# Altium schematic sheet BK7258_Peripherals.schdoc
size 440 x 214 mm
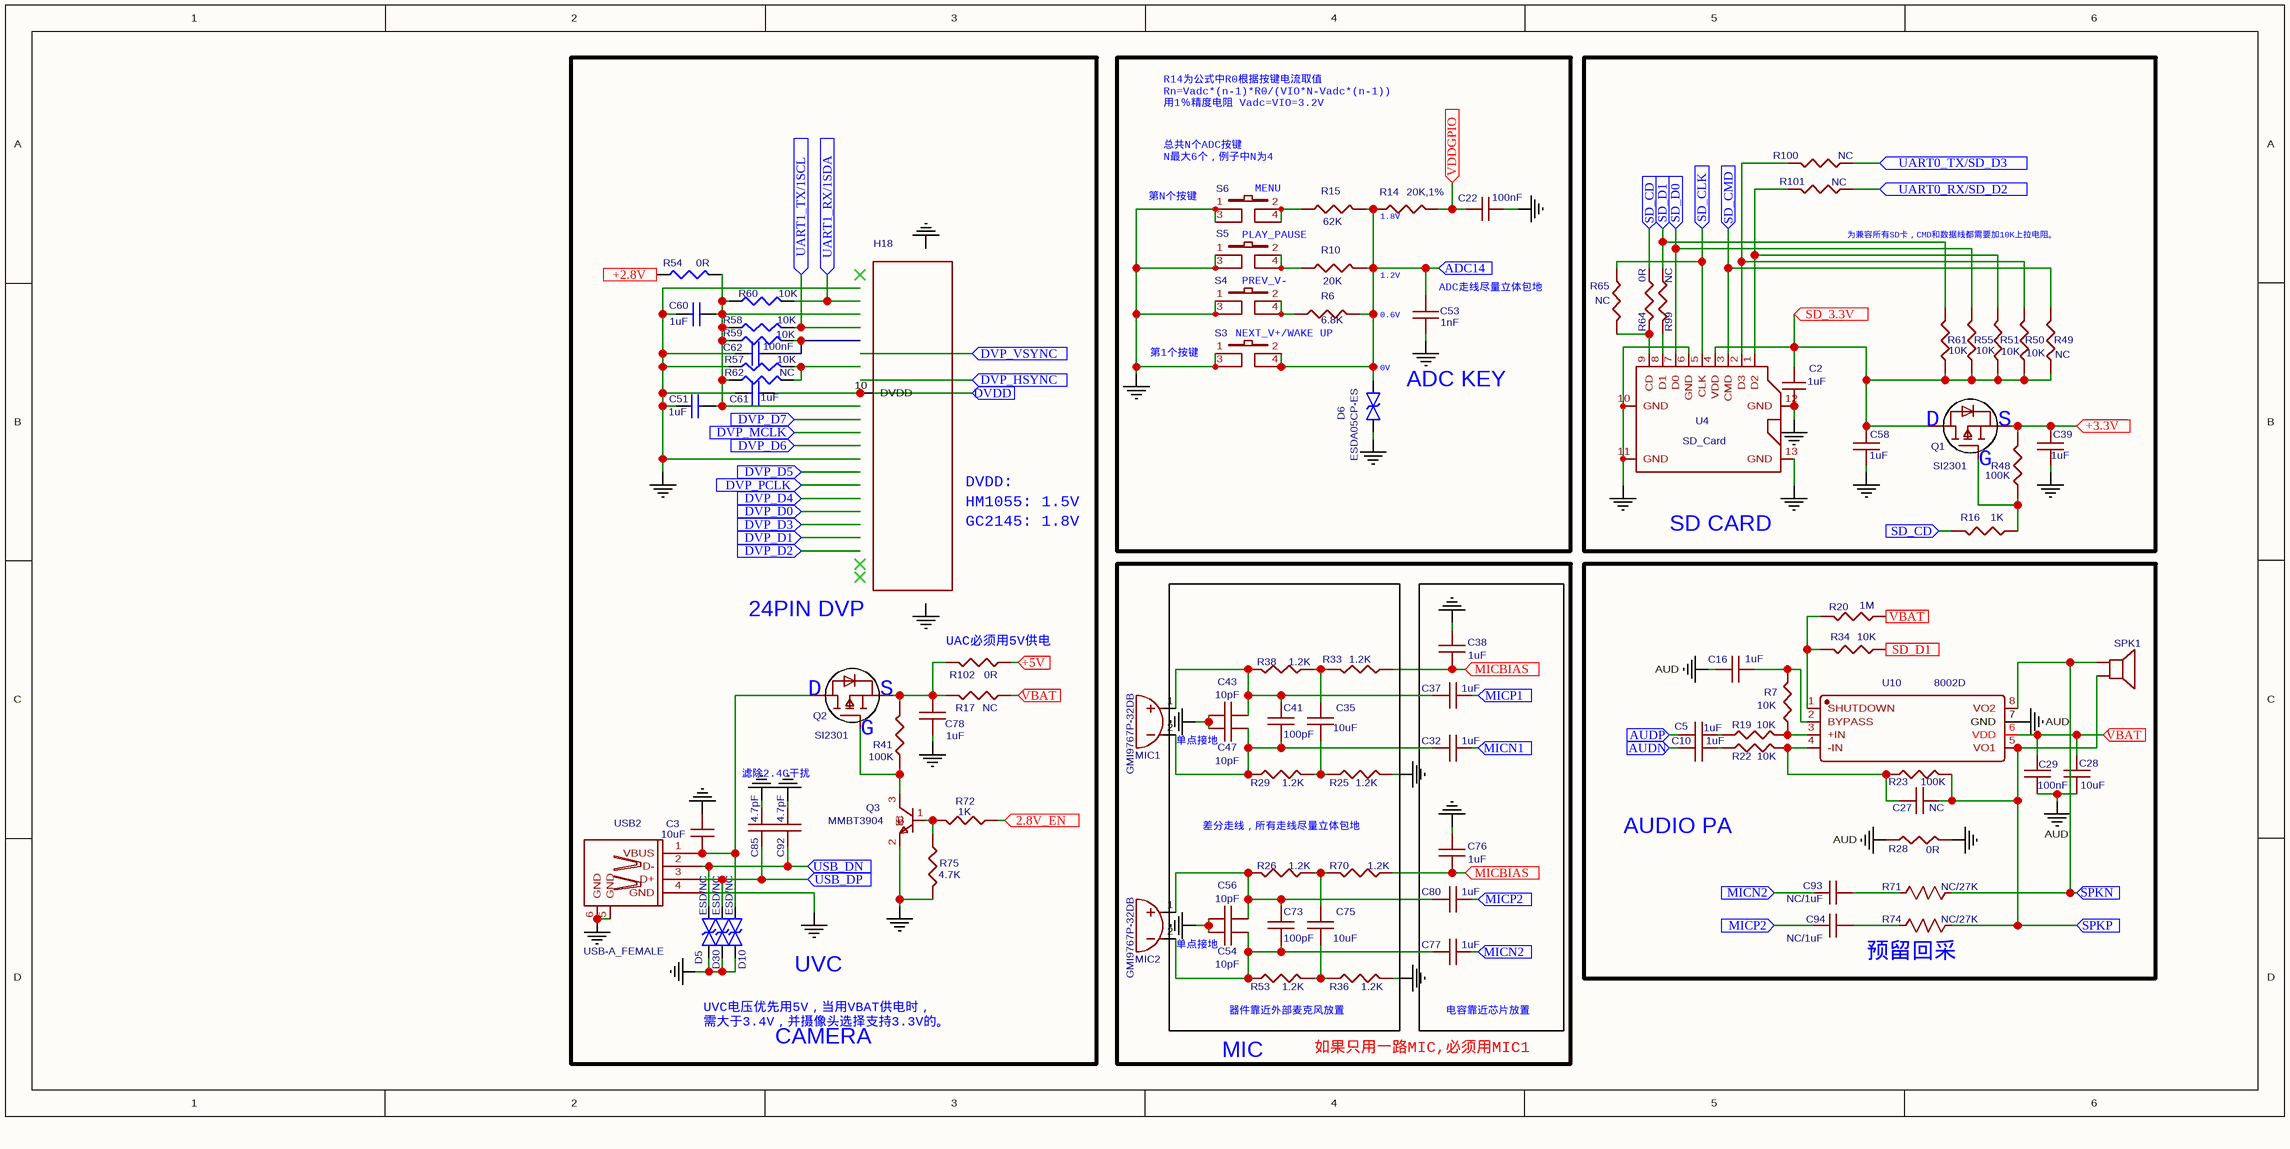
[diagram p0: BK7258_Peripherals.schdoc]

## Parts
C2  1uF  [C0402]
C3  10uF  [C0402]
C5  1uF  [C0402]
C10  1uF  [C0402]
C16  1uF  [C0402]
C22  100nF  [C0402]
C27  NC  [C0402]
C28  10uF  [C0603]
C29  100nF  [C0402]
C32  1uF  [C0402]
C35  10uF  [C0603]
C37  1uF  [C0402]
C38  1uF  [C0402]
C39  1uF  [C0402]
C41  100pF  [C0402]
C43  10pF  [C0402]
C47  10pF  [C0402]
C51  1uF  [C0402]
C53  1nF  [C0402]
C54  10pF  [C0402]
C56  10pF  [C0402]
C58  1uF  [C0402]
C60  1uF  [C0402]
C61  1uF  [C0402]
C62  100nF  [C0402]
C73  100pF  [C0402]
C75  10uF  [C0603]
C76  1uF  [C0402]
C77  1uF  [C0402]
C78  1uF  [C0603]
C80  1uF  [C0402]
C85  4.7pF  [C0603]
C92  4.7pF  [C0603]
C93  NC/1uF  [C0402]
C94  NC/1uF  [C0402]
D5  ESD/NC  [ESD0402]
D6  ESDA05CP-ES  [DFN1006-2L-BI]
D10  ESD/NC  [ESD0402]
D30  ESD/NC  [ESD0402]
H18  PAS6329  [FPC-24PIN]  (value not drawn)
MIC1  GMI9767P-32DB  [MIC-TH_BD9.7-P2.54-D0.8-L-FD]
MIC2  GMI9767P-32DB  [MIC-TH_BD9.7-P2.54-D0.8-L-FD]
Q1  SI2301  [SOT-23]
Q2  SI2301  [SOT-23]
Q3  MMBT3904  [SOT-23]
R6  6.8K  [R0402]
R7  10K  [R0402]
R10  20K  [R0402]
R14  20K,1%  [R0402]
R15  62K  [R0402]
R16  1K  [R0402]
R17  NC  [R0402]
R19  10K  [R0402]
R20  1M  [R0402]
R22  10K  [R0402]
R23  100K  [R0402]
R25  1.2K  [R0402]
R26  1.2K  [R0402]
R28  0R  [R0402]
R29  1.2K  [R0402]
R33  1.2K  [R0402]
R34  10K  [R0402]
R36  1.2K  [R0402]
R38  1.2K  [R0402]
R41  100K  [R0402]
R48  100K  [R0402]
R49  NC  [R0402]
R50  10K  [R0402]
R51  10K  [R0402]
R53  1.2K  [R0402]
R54  0R  [R0402]
R55  10K  [R0402]
R57  10K  [R0402]
R58  10K  [R0402]
R59  10K  [R0402]
R60  10K  [R0402]
R61  10K  [R0402]
R62  NC  [R0402]
R64  0R  [R0402]
R65  NC  [R0402]
R70  1.2K  [R0402]
R71  NC/27K  [R0402]
R72  1K  [R0402]
R74  NC/27K  [R0402]
R75  4.7K  [R0402]
R99  NC  [R0402]
R100  NC  [R0402]
R101  NC  [R0402]
R102  0R  [R0402]
S3  KEY  [4PIN_SWITCH_SMD_4.5MM]  (value not drawn)
S4  KEY  [4PIN_SWITCH_SMD_4.5MM]  (value not drawn)
S5  KEY  [4PIN_SWITCH_SMD_4.5MM]  (value not drawn)
S6  KEY  [4PIN_SWITCH_SMD_4.5MM]  (value not drawn)
SPK1  喇叭  [H02X1]  (value not drawn)
U4  SD_Card  [TF_SOCKET]
U10  8002D  [SO8_150]
USB2  USB-A_FEMALE  [USB_A_FEMALE]

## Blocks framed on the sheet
ADC KEY: C22 C53 D6 R6 R10 R14 R15 S3-S6
MIC: C35 C41 C43 C47 C54 C56 C73 C75 MIC1 MIC2 R25 R26 R29 R33 R36 R38 R53 R70
电容靠近芯片放置: C32 C37 C38 C76 C77 C80

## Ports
2.8V_EN (in), +2.8V (in), +3.3V (in), +5V (in), ADC14 (in), AUDN (in), AUDP (in), DVDD (in), DVP_D0 (in), DVP_D1 (in), DVP_D2 (in), DVP_D3 (in), DVP_D4 (in), DVP_D5 (in), DVP_D6 (in), DVP_D7 (in), DVP_HSYNC (in), DVP_MCLK (in), DVP_PCLK (in), DVP_VSYNC (in), MICBIAS (in), MICN1 (in), MICN2 (in), MICP1 (in), MICP2 (in), SD_3.3V (in), SD_CD (in), SD_CLK (in), SD_CMD (in), SD_D0 (in), SD_D1 (in), SPKN (in), SPKP (in), UART0_RX/SD_D2 (in), UART0_TX/SD_D3 (in), UART1_RX/1SDA (in), UART1_TX/1SCL (in), USB_DN (in), USB_DP (in), VBAT (in), VDDGPIO (in)

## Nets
AUD: C16.2 C28.2 C29.2 R28.2 U10.7(GND)
GGND: C2.2 C3.1 C22.1 C38.1 C39.1 C43.1 C47.1 C51.1 C53.1 C54.1 C56.1 C58.1 C60.2 C61.2 C62.2 C76.1 C78.1 C85.2 C92.2 D5.2 D6.1 D10.2 D30.2 Q3.2(E) R25.1 R28.1 R36.1 R57.1 R75.1 S3.1 S3.3 S4.1 S4.3 S5.1 S5.3 S6.1 S6.3 U4.6(GND) U4.10(GND) U4.11(GND) U4.12(GND) U4.13(GND) USB2.4(GND) USB2.5(GND) USB2.6(GND)
2.8V_EN: R72.1 ; port 2.8V_EN
+2.8V: R54.1 ; port +2.8V
+3.3V: C39.2 Q1.2(S) R48.2 ; port +3.3V
+5V: R102.1 ; port +5V
ADC14: C53.2 D6.2 R6.2 R10.2 R14.1 R15.2 S3.2 S3.4 ; port ADC14
AUDN: C10.2 ; port AUDN
AUDP: C5.2 ; port AUDP
DVDD: C61.1 H18.10(DVDD) ; port DVDD
MICBIAS: C38.2 C76.2 R33.1 R70.1 ; port MICBIAS
MICN1: C32.1 ; port MICN1
MICN2: C77.1 C93.1 ; port MICN2
MICP1: C37.1 ; port MICP1
MICP2: C80.1 C94.1 ; port MICP2
SD_3.3V: C2.1 C58.2 Q1.3(D) R49.2 R50.2 R51.2 R55.2 R61.2 U4.4(VDD) ; port SD_3.3V
SD_CD: R16.1 R64.2 ; port SD_CD
SD_CLK: R65.2 U4.5(CLK) ; port SD_CLK
SD_CMD: R49.1 U4.3(CMD) ; port SD_CMD
SD_D0: R55.1 U4.7(D0) ; port SD_D0
SD_D1: R34.2 R61.1 R99.2 ; port SD_D1
SPKN: R71.1 SPK1.1 U10.8(VO2) ; port SPKN
SPKP: C27.1 R23.1 R74.1 SPK1.2 U10.5(VO1) ; port SPKP
UART0_RX/SD_D2: R101.2 ; port UART0_RX/SD_D2
UART0_TX/SD_D3: R100.2 ; port UART0_TX/SD_D3
UART1_RX/1SDA: R60.2 ; port UART1_RX/1SDA
UART1_TX/1SCL: R58.2 ; port UART1_TX/1SCL
USB_DN: C92.1 D5.1 USB2.2(D-) ; port USB_DN
USB_DP: C85.1 D30.1 USB2.3(D+) ; port USB_DP
VBAT: C28.1 C29.1 R17.1 R20.2 U10.6(VDD) ; port VBAT
VDDGPIO: C22.2 R14.2 ; port VDDGPIO
NetC3_2: C3.2 D10.1 Q2.3(D) USB2.1(VBUS)
NetC5_1: C5.1 R19.2
NetC10_1: C10.1 R22.2
NetC16_1: C16.1 R7.1 U10.2(BYPASS)
NetC27_2: C27.2 R22.1 R23.2 U10.4(-IN)
NetC32_2: C32.2 C41.2 C47.2 MIC1.2 R29.2
NetC35_1: C35.1 R33.2 R38.2
NetC35_2: C35.2 R25.2 R29.1
NetC37_2: C37.2 C41.1 C43.2 MIC1.1 R38.1
NetC51_2: C51.2 C60.1 R54.2 R58.1 R59.1 R60.1 R62.1
NetC54_2: C54.2 C73.2 C77.2 MIC2.2 R53.2
NetC56_2: C56.2 C73.1 C80.2 MIC2.1 R26.1
NetC62_1: C62.1 R59.2
NetC75_1: C75.1 R26.2 R70.2
NetC75_2: C75.2 R36.2 R53.1
NetC78_2: C78.2 Q2.2(S) R17.2 R41.2 R102.2
NetC93_2: C93.2 R71.2
NetC94_2: C94.2 R74.2
NetQ1_1: Q1.1(G) R16.2 R48.1
NetQ2_1: Q2.1(G) Q3.3(C) R41.1
NetQ3_1: Q3.1(B) R72.2 R75.2
NetR6_1: R6.1 S4.2 S4.4
NetR7_2: R7.2 R19.1 U10.3(+IN)
NetR10_1: R10.1 S5.2 S5.4
NetR15_1: R15.1 S6.2 S6.4
NetR20_1: R20.1 R34.1 U10.1(SHUTDOWN)
NetR50_1: R50.1 R100.1 U4.2(D3)
NetR51_1: R51.1 R101.1 U4.1(D2)
NetR57_2: R57.2 R62.2
NetR64_1: R64.1 R65.1 U4.9(CD)
NetR99_1: R99.1 U4.8(D1)

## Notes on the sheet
- (near S6) R14为公式中R0根据按键电流取值
  Rn=Vadc*(n-1)*R0/(VIO*N-Vadc*(n-1))
  用1％精度电阻 Vadc=VIO=3.2V
- 总共N个ADC按键
  N最大6个，例子中N为4
- 第N个按键
- (near S6) MENU
- (near R14) 1.8V
- (near R101) 为兼容所有SD卡，CMD和数据线都需要加10K上拉电阻。
- PLAY_PAUSE
- PREV_V-
- 1.2V
- 第1个按键
- NEXT_V+/WAKE UP
- 0.6V
- (near C53) ADC走线尽量立体包地
- (near D6) 0V
- DVDD:
- (near Q1) D
- (near Q1) G
- (near Q1) S
- GC2145: 1.8V
- HM1055: 1.5V
- SD CARD
- 24PIN DVP
- (near R102) UAC必须用5V供电
- (near Q2) D
- (near Q2) G
- (near Q2) S
- (near MIC1) 单点接地
- 滤除2.4G干扰
- 差分走线，所有走线尽量立体包地
- AUDIO PA
- UVC电压优先用5V，当用VBAT供电时，
  需大于3.4V，并摄像头选择支持3.3V的。
- UVC
- (near MIC2) 单点接地
- (near R53) 器件靠近外部麦克风放置
- (near R74) 预留回采
- CAMERA
- 如果只用一路MIC,必须用MIC1
- Labels drawn without touching a wire or pin: GGND

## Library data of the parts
C2 = 1uF: Manufacturer Part Number: 06035A101KAT2A; Manufacturer: AVX; APN: C029-0
C3 = 10uF: Manufacturer Part Number: 06035A101KAT2A; Manufacturer: AVX; APN: C029-0
C5 C10 C16 C32 C37-C39 C58 C76-C78 C80 = 1uF: Manufacturer: AVX; Manufacturer Part Number: 0805ZC105KAT2A; APN: C071-0
C22 = 100nF: Manufacturer Part Number: 06035A101KAT2A; Manufacturer: AVX; APN: C029-0
C27 = NC: Manufacturer: AVX; Manufacturer Part Number: 0805ZC105KAT2A; APN: C071-0
C28 C35 C75 = 10uF: Manufacturer: AVX; Manufacturer Part Number: 0805ZC105KAT2A; APN: C071-0
C29 = 100nF: Manufacturer: AVX; Manufacturer Part Number: 0805ZC105KAT2A; APN: C071-0
C41 C73 = 100pF: Manufacturer: AVX; Manufacturer Part Number: 0805ZC105KAT2A; APN: C071-0
C43 C47 C54 C56 = 10pF: Manufacturer: AVX; Manufacturer Part Number: 0805ZC105KAT2A; APN: C071-0
C51 C60 C61 = 1uF: Manufacturer Part Number: 08055A390JATMA; Manufacturer: AVX; APN: C012-0
C53 = 1nF: Manufacturer: AVX; Manufacturer Part Number: 0805ZC105KAT2A; APN: C071-0
C62 = 100nF: Manufacturer Part Number: 08055A390JATMA; Manufacturer: AVX; APN: C012-0
C85 C92 = 4.7pF: Manufacturer: AVX; Manufacturer Part Number: 0805ZC105KAT2A; APN: C071-0
C93 C94 = NC/1uF: Manufacturer Part Number: 06035A101KAT2A; Manufacturer: AVX; APN: C029-0
D5 D10 D30 = ESD/NC: Contributor: D-MAN
D6 = ESDA05CP-ES: BOM_Manufacturer: SOT23-5_SGM2019; Contributor: D-MAN
H18 = PAS6329: Manufacturer Part Number: TPEG20DSGAQ; Manufacturer: Crane; APN: H07-0
MIC1 MIC2 = GMI9767P-32DB: Manufacturer: INGHAi(赢海); Contributor: LCSC
Q1 Q2 = SI2301: Manufacturer: DOWO(东沃); Contributor: lcsc
Q3 = MMBT3904: Manufacturer: PANJIT International; Contributor: LCSC
R6 = 6.8K: Manufacturer Part Number: RK73H2AT4752F; Manufacturer: KOA; APN: R096-0
R7 R19 R22 R34 R50 R51 R55 R61 = 10K: Manufacturer Part Number: RK73H2AT1004F; Manufacturer: KOA; APN: R028-0
R10 = 20K: Manufacturer Part Number: RK73H2AT4752F; Manufacturer: KOA; APN: R096-0
R14 = 20K,1%: Manufacturer Part Number: RK73H2AT4752F; Manufacturer: KOA; APN: R096-0
R15 = 62K: Manufacturer Part Number: RK73H2AT4752F; Manufacturer: KOA; APN: R096-0
R16 R72 = 1K: Manufacturer Part Number: RM73B1JT240J; Manufacturer: KOA; APN: R125-0
R17 R62 R65 R99-R101 = NC: Manufacturer Part Number: RM73B1JT240J; Manufacturer: KOA; APN: R125-0
R20 = 1M: Manufacturer Part Number: RK73H2AT1004F; Manufacturer: KOA; APN: R028-0
R23 = 100K: Manufacturer Part Number: RK73H2AT1004F; Manufacturer: KOA; APN: R028-0
R25 R26 R29 R33 R36 R38 R53 R70 = 1.2K: Manufacturer Part Number: RK73H2AT1004F; Manufacturer: KOA; APN: R028-0
R28 = 0R: Manufacturer Part Number: RK73H2AT1004F; Manufacturer: KOA; APN: R028-0
R41 R48 = 100K: Manufacturer Part Number: RK73H2AT4752F; Manufacturer: KOA; APN: R096-0
R49 = NC: Manufacturer Part Number: RK73H2AT1004F; Manufacturer: KOA; APN: R028-0
R54 R64 R102 = 0R: Manufacturer Part Number: RM73B1JT240J; Manufacturer: KOA; APN: R125-0
R57-R60 = 10K: Manufacturer Part Number: RM73B1JT240J; Manufacturer: KOA; APN: R125-0
R71 R74 = NC/27K: nameAlias: Value(Ω); Contributor: LCEDA_Lib
R75 = 4.7K: Manufacturer Part Number: RK73H2AT4752F; Manufacturer: KOA; APN: R096-0
S3-S6 = KEY: Manufacturer Part Number: EP11SD1ABE; Manufacturer: C & K; APN: S001-0
SPK1 = 喇叭: Manufacturer: S&S; Manufacturer Part: SFN-12055PA6.5; Frequency: 4000Hz
U10 = 8002D: Manufacturer: IDCHIP; Contributor: LCSC
USB2 = USB-A_FEMALE: APN: U095-0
